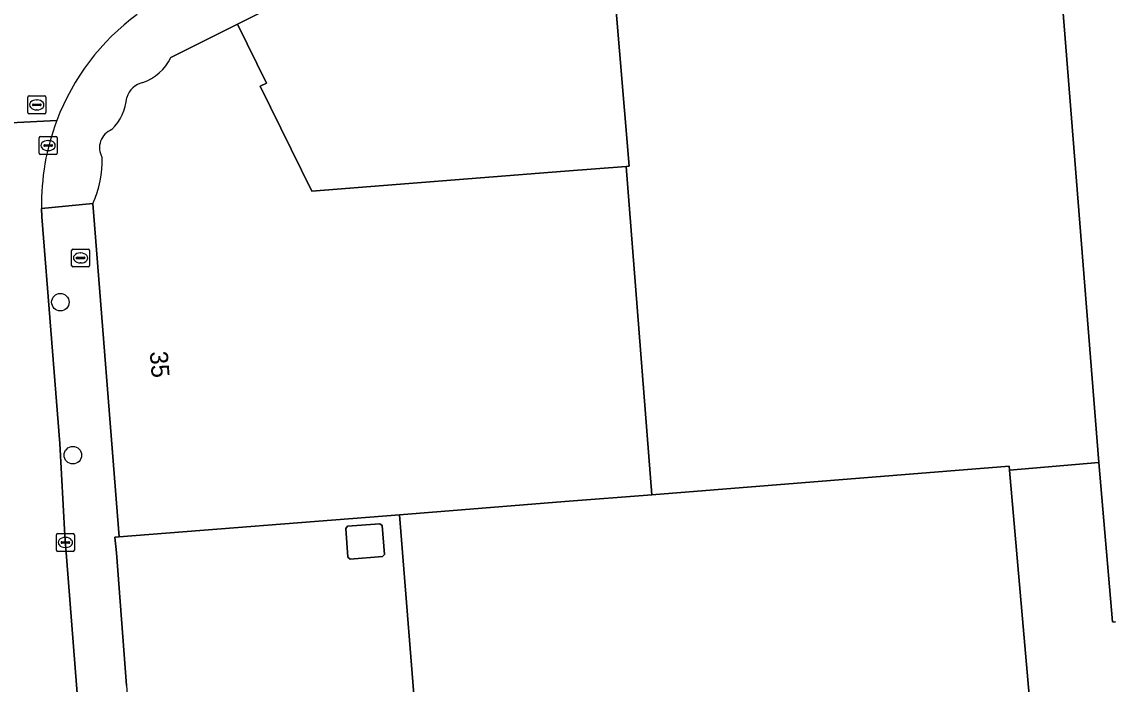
# Model space of a CAD drawing. Extents: x 157793 to 159380, y 380877 to 382313.
# Drawn here: x 157969.6 to 158030.4, y 381419.3 to 381456.3 of the extents above; entities that cross this region are included whole.
import ezdxf

# ---------------------------------------------------------------- set-up
doc = ezdxf.new("R2010")
doc.units = 0
for name, color, linetype in [('IMGEO_Boom', 7, 'Continuous'), ('IMGEO_Brandkraan', 7, 'Continuous'), ('IMGEO_Erf', 7, 'Continuous'), ('IMGEO_Kolk', 7, 'Continuous'), ('IMGEO_Lage_trafo', 7, 'Continuous'), ('IMGEO_Pand', 7, 'Continuous'), ('IMGEO_Pand_nummerreeks', 7, 'Continuous'), ('IMGEO_Rijbaan_lokaal_gesloten', 7, 'Continuous'), ('IMGEO_Rioolput', 7, 'Continuous'), ('IMGEO_Voetpad_open', 7, 'Continuous')]:
    doc.layers.add(name, color=color, linetype=linetype)

msp = doc.modelspace()

# ---------------------------------------------------------------- linework, layer by layer
at = {"layer": 'IMGEO_Boom'}
for centre in [(157971.795, 381440.642), (157972.492, 381432.089)]:
    msp.add_circle(centre, 0.489, dxfattribs=at)
at = {"layer": 'IMGEO_Brandkraan'}
for p, q in [((157972.423, 381442.688), (157972.423, 381443.54)), ((157972.498, 381443.614), (157973.35, 381443.614)), ((157973.424, 381443.54), (157973.424, 381442.688)), ((157972.682, 381443.108), (157972.682, 381443.12)), ((157973.12, 381443.071), (157972.722, 381443.071)), ((157972.725, 381443.157), (157973.123, 381443.157)), ((157972.911, 381443.394), (157972.936, 381443.394)), ((157973.166, 381443.12), (157973.166, 381443.108)), ((157973.35, 381442.614), (157972.498, 381442.614)), ((157972.934, 381442.834), (157972.909, 381442.834))]:
    msp.add_line(p, q, dxfattribs=at)
for points in [[(157972.423, 381442.688), (157972.423, 381443.54)], [(157972.498, 381443.614), (157973.35, 381443.614)], [(157973.424, 381443.54), (157973.424, 381442.688)], [(157973.35, 381442.614), (157972.498, 381442.614)]]:
    msp.add_lwpolyline(points, dxfattribs=at)
for centre, radius, start, end in [((157972.5, 381443.538), 0.0765, 91.55205, 178.44795), ((157972.5, 381443.538), 0.0765, 91.55205, 178.44795), ((157973.348, 381443.538), 0.0765, 1.55205, 88.44795), ((157973.348, 381443.538), 0.0765, 1.55205, 88.44795), ((157972.722, 381443.117), 0.0403, 85.87752, 175.75265), ((157972.719, 381443.107), 0.0366, 178.93798, 274.71019), ((157973.123, 381443.114), 0.043, 264.86636, 352.45326), ((157973.127, 381443.119), 0.0386, 1.73085, 96.63898), ((157972.5, 381442.69), 0.0765, 181.55205, 268.44795), ((157972.5, 381442.69), 0.0765, 181.55205, 268.44795), ((157973.348, 381442.69), 0.0765, 271.55205, 358.44795), ((157973.348, 381442.69), 0.0765, 271.55205, 358.44795)]:
    msp.add_arc(centre, radius, start, end, dxfattribs=at)
for centre, major_axis, ratio, start_param, end_param in [((157972.91, 381443.114), (-0.387, 0.002), 0.722429, 4.712389, 7.853982), ((157972.935, 381443.114), (-0.39, 0.002), 0.717154, 1.570796, 4.712389)]:
    msp.add_ellipse(centre, major_axis=major_axis, ratio=ratio, start_param=start_param, end_param=end_param, dxfattribs=at)
at = {"layer": 'IMGEO_Erf'}
for points in [[(158019.981, 381475.214), (158018.159, 381474.325), (158017.68, 381474.092), (158016.82, 381473.672), (158008.741, 381469.656), (158007.951, 381469.263), (158002.249, 381466.432), (158001.969, 381466.293), (158000, 381465.316), (157996.346, 381463.5), (157993.12, 381461.891), (157981.69, 381456.19), (157983.31, 381452.88), (157982.97, 381452.72), (157985.85, 381446.85), (158000, 381447.964), (158003.413, 381448.233), (158003.581, 381448.246), (158002.787, 381457.829), (158027.635, 381459.625), (158027.622, 381459.792)], [(157988.001, 381426.275), (157987.87, 381426.386), (157987.742, 381427.99), (157987.853, 381428.118), (157989.655, 381428.261), (157989.786, 381428.151), (157989.913, 381426.546), (157989.803, 381426.418)]]:
    msp.add_lwpolyline(points, close=True, dxfattribs=at)
msp.add_lwpolyline([(158030.615, 381422.766), (158029.837, 381431.674), (158024.855, 381431.246), (158028.741, 381386.724), (158000, 381384.363), (157994.33, 381383.92), (157990.751, 381428.76), (157975.08, 381427.53), (157974.847, 381427.508), (157974.929, 381426.631), (157975.487, 381419.212), (157977.357, 381395.476), (157977.741, 381390.203), (157978.379, 381382.688), (157978.576, 381382.684), (157984.575, 381306.939), (157995.499, 381307.813), (157996.345, 381297.089), (157996.832, 381290.907), (157997.351, 381285.965), (157997.859, 381279.57), (158000, 381252.62)], dxfattribs=at)
at = {"layer": 'IMGEO_Kolk'}
for p, q in [((157970.608, 381448.975), (157970.608, 381449.827)), ((157970.683, 381449.901), (157971.535, 381449.901)), ((157971.096, 381449.681), (157971.121, 381449.681)), ((157971.609, 381449.827), (157971.609, 381448.975)), ((157970.867, 381449.395), (157970.867, 381449.407)), ((157971.305, 381449.358), (157970.907, 381449.358)), ((157970.91, 381449.444), (157971.308, 381449.444)), ((157971.119, 381449.121), (157971.094, 381449.121)), ((157971.351, 381449.407), (157971.351, 381449.395)), ((157971.535, 381448.901), (157970.683, 381448.901)), ((157971.574, 381426.784), (157971.574, 381427.636)), ((157971.649, 381427.71), (157972.501, 381427.71)), ((157971.833, 381427.204), (157971.833, 381427.216)), ((157972.271, 381427.167), (157971.873, 381427.167)), ((157971.876, 381427.253), (157972.274, 381427.253)), ((157972.062, 381427.49), (157972.087, 381427.49)), ((157972.317, 381427.216), (157972.317, 381427.204)), ((157972.575, 381427.636), (157972.575, 381426.784)), ((157972.501, 381426.71), (157971.649, 381426.71)), ((157972.085, 381426.93), (157972.06, 381426.93))]:
    msp.add_line(p, q, dxfattribs=at)
for points in [[(157970.608, 381448.975), (157970.608, 381449.827)], [(157970.683, 381449.901), (157971.535, 381449.901)], [(157971.609, 381449.827), (157971.609, 381448.975)], [(157971.535, 381448.901), (157970.683, 381448.901)], [(157971.574, 381426.784), (157971.574, 381427.636)], [(157971.649, 381427.71), (157972.501, 381427.71)], [(157972.575, 381427.636), (157972.575, 381426.784)], [(157972.501, 381426.71), (157971.649, 381426.71)]]:
    msp.add_lwpolyline(points, dxfattribs=at)
for centre, radius, start, end in [((157970.685, 381449.825), 0.0765, 91.55205, 178.44795), ((157970.685, 381449.825), 0.0765, 91.55205, 178.44795), ((157971.533, 381449.825), 0.0765, 1.55205, 88.44795), ((157971.533, 381449.825), 0.0765, 1.55205, 88.44795), ((157970.907, 381449.404), 0.0403, 85.87752, 175.75265), ((157970.904, 381449.394), 0.0366, 178.93798, 274.71019), ((157971.308, 381449.401), 0.043, 264.86636, 352.45326), ((157971.312, 381449.406), 0.0386, 1.73085, 96.63898), ((157970.685, 381448.977), 0.0765, 181.55205, 268.44795), ((157970.685, 381448.977), 0.0765, 181.55205, 268.44795), ((157971.533, 381448.977), 0.0765, 271.55205, 358.44795), ((157971.533, 381448.977), 0.0765, 271.55205, 358.44795), ((157971.651, 381427.634), 0.0765, 91.55205, 178.44795), ((157971.651, 381427.634), 0.0765, 91.55205, 178.44795), ((157971.873, 381427.213), 0.0403, 85.87752, 175.75265), ((157971.87, 381427.203), 0.0366, 178.93798, 274.71019), ((157972.274, 381427.21), 0.043, 264.86636, 352.45326), ((157972.278, 381427.215), 0.0386, 1.73085, 96.63898), ((157972.499, 381427.634), 0.0765, 1.55205, 88.44795), ((157972.499, 381427.634), 0.0765, 1.55205, 88.44795), ((157971.651, 381426.786), 0.0765, 181.55205, 268.44795), ((157971.651, 381426.786), 0.0765, 181.55205, 268.44795), ((157972.499, 381426.786), 0.0765, 271.55205, 358.44795), ((157972.499, 381426.786), 0.0765, 271.55205, 358.44795)]:
    msp.add_arc(centre, radius, start, end, dxfattribs=at)
for centre, major_axis, ratio, start_param, end_param in [((157971.095, 381449.401), (-0.387, 0.002), 0.722429, 4.712389, 7.853982), ((157971.12, 381449.401), (-0.39, 0.002), 0.717154, 1.570796, 4.712389), ((157972.061, 381427.21), (-0.387, 0.002), 0.722429, 4.712389, 7.853982), ((157972.086, 381427.21), (-0.39, 0.002), 0.717154, 1.570796, 4.712389)]:
    msp.add_ellipse(centre, major_axis=major_axis, ratio=ratio, start_param=start_param, end_param=end_param, dxfattribs=at)
at = {"layer": 'IMGEO_Lage_trafo'}
msp.add_lwpolyline([(157988.001, 381426.275), (157989.803, 381426.418), (157989.913, 381426.546), (157989.786, 381428.151), (157989.655, 381428.261), (157987.853, 381428.118), (157987.742, 381427.99), (157987.87, 381426.386)], close=True, dxfattribs=at)
at = {"layer": 'IMGEO_Pand'}
for points in [[(158076.026, 381445.793), (158073.487, 381445.554), (158072.051, 381463.055), (158027.635, 381459.625), (158029.837, 381431.674), (158030.615, 381422.766), (158030.753, 381422.778), (158050.521, 381424.443), (158058.219, 381425.091), (158077.503, 381426.615)], [(158027.635, 381459.625), (158002.787, 381457.829), (158003.581, 381448.246), (158003.413, 381448.233), (158004.864, 381429.882), (158024.836, 381431.469), (158024.855, 381431.246), (158029.837, 381431.674)], [(158004.864, 381429.882), (158000, 381429.495), (157990.751, 381428.76), (157994.33, 381383.92), (158000, 381384.363), (158028.741, 381386.724), (158024.855, 381431.246), (158024.836, 381431.469)]]:
    msp.add_lwpolyline(points, close=True, dxfattribs=at)
msp.add_lwpolyline([(157973.61, 381446.16), (157975.08, 381427.53), (157990.751, 381428.76), (158000, 381429.495), (158004.864, 381429.882), (158003.413, 381448.233), (158000, 381447.964), (157985.85, 381446.85), (157982.97, 381452.72), (157983.31, 381452.88), (157981.69, 381456.19), (157977.963, 381454.315)], dxfattribs=at)
for centre, radius, start, end in [((157975.564, 381455.426), 2.643, 288.42744, 335.15286), ((157976.637, 381451.776), 1.167, 101.70202, 164.56841), ((157972.608, 381452.348), 2.915, 315.19744, 354.83531), ((157975.062, 381449.285), 1.08, 110.85888, 210.60359), ((157968.143, 381448.609), 5.991, 335.87325, 1.20752)]:
    msp.add_arc(centre, radius, start, end, dxfattribs=at)
at = {"layer": 'IMGEO_Rijbaan_lokaal_gesloten'}
for points in [[(157964.606, 381452.598), (157964.186, 381450.429), (157971.593, 381450.806)], [(157971.593, 381450.806), (157964.186, 381450.429)], [(157972.04, 381427.592), (157971.761, 381432.744), (157970.763, 381445.421), (157970.745, 381445.878)], [(157991.177, 381259.749), (157988.013, 381267.372), (157986.63, 381271.474), (157984.537, 381279.44), (157984.01, 381282.256), (157982.89, 381291.114), (157981.742, 381305.105), (157981.728, 381305.287), (157975.516, 381383.424), (157975.082, 381388.727), (157974.481, 381396.457), (157972.816, 381417.811), (157972.04, 381427.592)]]:
    msp.add_lwpolyline(points, dxfattribs=at)
for centre, radius, start, end in [((157983.865, 381446.158), 13.123, 126.30666, 159.25456), ((157983.857, 381446.159), 13.115, 159.24641, 181.22615)]:
    msp.add_arc(centre, radius, start, end, dxfattribs=at)
at = {"layer": 'IMGEO_Rioolput'}
for p, q in [((157969.976, 381451.248), (157969.976, 381452.1)), ((157970.051, 381452.174), (157970.903, 381452.174)), ((157970.977, 381452.1), (157970.977, 381451.248)), ((157970.235, 381451.668), (157970.235, 381451.68)), ((157970.673, 381451.631), (157970.275, 381451.631)), ((157970.278, 381451.717), (157970.676, 381451.717)), ((157970.464, 381451.954), (157970.489, 381451.954)), ((157970.719, 381451.68), (157970.719, 381451.668)), ((157970.903, 381451.174), (157970.051, 381451.174)), ((157970.487, 381451.394), (157970.462, 381451.394))]:
    msp.add_line(p, q, dxfattribs=at)
for points in [[(157969.976, 381451.248), (157969.976, 381452.1)], [(157970.051, 381452.174), (157970.903, 381452.174)], [(157970.977, 381452.1), (157970.977, 381451.248)], [(157970.903, 381451.174), (157970.051, 381451.174)]]:
    msp.add_lwpolyline(points, dxfattribs=at)
for centre, radius, start, end in [((157970.053, 381452.098), 0.0765, 91.55205, 178.44795), ((157970.053, 381452.098), 0.0765, 91.55205, 178.44795), ((157970.901, 381452.098), 0.0765, 1.55205, 88.44795), ((157970.901, 381452.098), 0.0765, 1.55205, 88.44795), ((157970.275, 381451.677), 0.0403, 85.87752, 175.75265), ((157970.272, 381451.667), 0.0366, 178.93798, 274.71019), ((157970.676, 381451.674), 0.043, 264.86636, 352.45326), ((157970.68, 381451.679), 0.0386, 1.73085, 96.63898), ((157970.053, 381451.25), 0.0765, 181.55205, 268.44795), ((157970.053, 381451.25), 0.0765, 181.55205, 268.44795), ((157970.901, 381451.25), 0.0765, 271.55205, 358.44795), ((157970.901, 381451.25), 0.0765, 271.55205, 358.44795)]:
    msp.add_arc(centre, radius, start, end, dxfattribs=at)
for centre, major_axis, ratio, start_param, end_param in [((157970.463, 381451.674), (-0.387, 0.002), 0.722429, 4.712389, 7.853982), ((157970.488, 381451.674), (-0.39, 0.002), 0.717154, 1.570796, 4.712389)]:
    msp.add_ellipse(centre, major_axis=major_axis, ratio=ratio, start_param=start_param, end_param=end_param, dxfattribs=at)
at = {"layer": 'IMGEO_Voetpad_open'}
for points in [[(157977.963, 381454.315), (157981.69, 381456.19), (157993.12, 381461.891), (157996.346, 381463.5), (158000, 381465.316), (158001.969, 381466.293), (158002.249, 381466.432), (158007.951, 381469.263), (158008.741, 381469.656), (158016.82, 381473.672), (158017.68, 381474.092), (158018.159, 381474.325), (158019.981, 381475.214), (158022.566, 381476.498), (158024.363, 381477.391)], [(157975.487, 381419.212), (157974.929, 381426.631), (157974.847, 381427.508), (157975.08, 381427.53), (157973.61, 381446.16), (157970.745, 381445.878), (157970.763, 381445.421), (157971.761, 381432.744), (157972.04, 381427.592), (157972.816, 381417.811), (157974.481, 381396.457), (157975.082, 381388.727), (157975.516, 381383.424)], [(157970.745, 381445.878), (157973.61, 381446.16)]]:
    msp.add_lwpolyline(points, dxfattribs=at)
for centre, radius, start, end in [((157983.865, 381446.158), 13.123, 126.30666, 159.25456), ((157975.564, 381455.426), 2.643, 288.42744, 335.15286), ((157976.637, 381451.776), 1.167, 101.70202, 164.56841), ((157972.608, 381452.348), 2.915, 315.19744, 354.83531), ((157983.857, 381446.159), 13.115, 159.24641, 181.22615), ((157975.062, 381449.285), 1.08, 110.85888, 210.60359), ((157968.143, 381448.609), 5.991, 335.87325, 1.20752)]:
    msp.add_arc(centre, radius, start, end, dxfattribs=at)

# ---------------------------------------------------------------- texts
at = {"layer": 'IMGEO_Pand_nummerreeks'}
msp.add_text('35', height=1, rotation=274.51157, dxfattribs=at).set_placement((157976.792, 381437.867))

doc.saveas('drawing.dxf')
